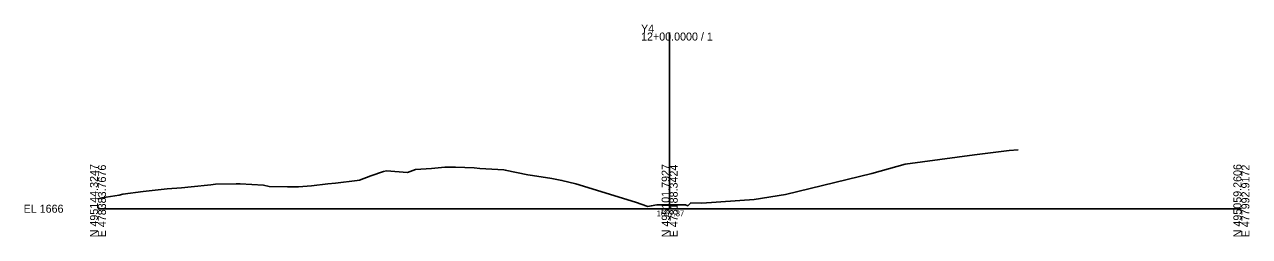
# Model space of a CAD drawing. Extents: x -26 to 403, y -10 to 5108.
# Drawn here: x -25.7 to 402.8, y 1990.3 to 2064.3 of the extents above; entities that cross this region are included whole.
import ezdxf

# ---------------------------------------------------------------- set-up
doc = ezdxf.new("R2010")
doc.units = 0
for name, color, linetype in [('Exist Cross Section Cell', 7, 'Continuous'), ('Exist XS Center Line Elevation Label', 7, 'Continuous'), ('Exist XS Ground Line', 7, 'Continuous')]:
    doc.layers.add(name, color=color, linetype=linetype)

msp = doc.modelspace()

# ---------------------------------------------------------------- linework, layer by layer
at = {"layer": 'Exist Cross Section Cell'}
for p, q in [((200, 2000), (200, 2061.55)), ((0, 2000), (200, 2000)), ((200, 2000), (400, 2000))]:
    msp.add_line(p, q, dxfattribs=at)
at = {"layer": 'Exist XS Ground Line'}
msp.add_lwpolyline([(0, 2003.51), (1.37, 2003.76), (7.44, 2004.72), (8.76, 2005.04), (15.85, 2005.96), (19, 2006.4), (24.25, 2006.97), (29.23, 2007.25), (32.66, 2007.68), (39.47, 2008.33), (41.07, 2008.53), (48.4, 2008.64), (49.71, 2008.64), (57.88, 2008.19), (59.94, 2007.78), (66.29, 2007.61), (70.18, 2007.68), (74.69, 2007.97), (80.41, 2008.68), (83.1, 2008.98), (90.65, 2009.89), (91.51, 2009.98), (95.43, 2011.53), (99.91, 2013.03), (100.89, 2013.19), (108.32, 2012.67), (111.12, 2013.75), (116.72, 2014.04), (121.36, 2014.51), (125.13, 2014.52), (131.59, 2014.23), (133.54, 2014.08), (141.94, 2013.59), (142.47, 2013.48), (150.35, 2011.84), (152.07, 2011.6), (158.76, 2010.6), (162.3, 2009.86), (167.16, 2008.68), (188.05, 2002.3), (192.36, 2000.74), (193.54, 2000.96), (195.53, 2001.35), (197.72, 2001.36), (200, 2001.37), (204.59, 2001.4), (205.59, 2001.31), (206.34, 2001.01), (206.83, 2001.47), (207.35, 2002.02), (211.23, 2001.94), (229.57, 2003.22), (240.52, 2004.99), (270.77, 2012.34), (282.4, 2015.62), (306.67, 2018.83), (318.73, 2020.34), (321.95, 2020.52)], dxfattribs=at)

# ---------------------------------------------------------------- texts
at = {"layer": 'Exist Cross Section Cell'}
for s, p in [('Y4', (190, 2061.55)), ('12+00.0000 / 1', (190, 2058.75)), ('EL 1666', (-26, 1998.6))]:
    msp.add_text(s, height=2.8, dxfattribs=at).set_placement(p)
for s, p in [('N 495144.3247', (0, 1990)), ('E 478383.7676', (2.8, 1990)), ('N 495101.7927', (200, 1990)), ('E 478188.3424', (202.8, 1990)), ('N 495059.2606', (400, 1990)), ('E 477992.9172', (402.8, 1990))]:
    msp.add_text(s, height=2.8, rotation=90, dxfattribs=at).set_placement(p)
at = {"layer": 'Exist XS Center Line Elevation Label'}
msp.add_text('1667.37', height=2, dxfattribs=at).set_placement((195.43, 1997.37))

doc.saveas('drawing.dxf')
